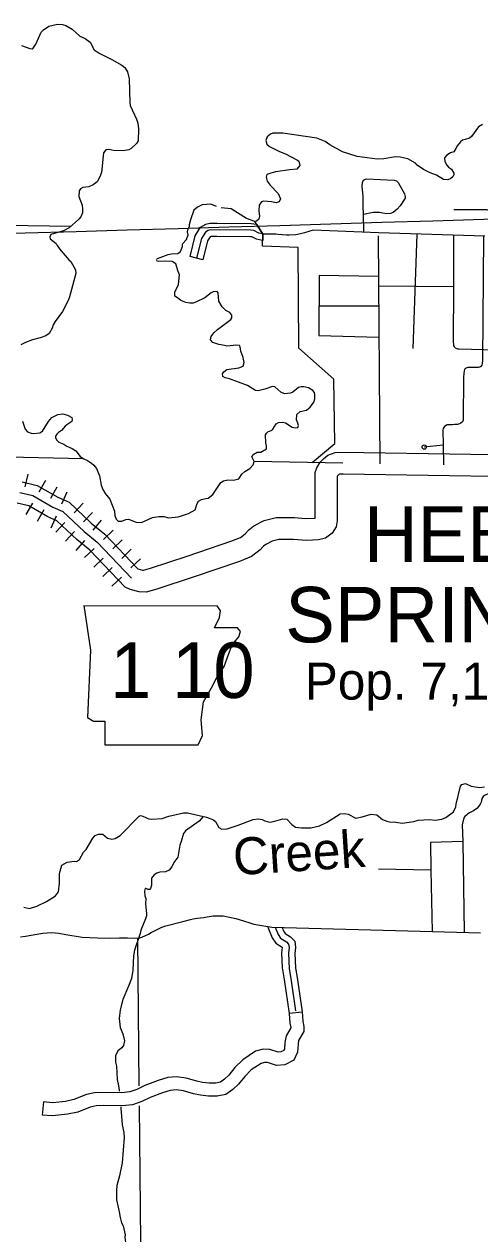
# Model space of a CAD drawing. Extents: x 1212896 to 1368412, y 378476 to 478763.
# Drawn here: x 1293079 to 1298275, y 413498 to 427303 of the extents above; entities that cross this region are included whole.
import ezdxf

# ---------------------------------------------------------------- set-up
doc = ezdxf.new("R2010")
doc.units = 0
for name, color, linetype in [('Level 10', 7, 'Continuous'), ('Level 21', 7, 'Continuous'), ('Level 29', 7, 'Continuous'), ('Level 31', 7, 'Continuous'), ('Level 33', 7, 'Continuous'), ('Level 34', 7, 'Continuous'), ('Level 35', 7, 'Continuous'), ('Level 45', 7, 'Continuous'), ('Level 46', 7, 'Continuous'), ('Level 5', 7, 'Continuous'), ('Level 6', 7, 'Continuous'), ('Level 60', 7, 'Continuous'), ('Level 9', 7, 'Continuous')]:
    doc.layers.add(name, color=color, linetype=linetype)

msp = doc.modelspace()

# ---------------------------------------------------------------- linework, layer by layer
at = {"layer": 'Level 10'}
for points in [[(1293057, 422081), (1293225, 422040), (1293462, 421904), (1293591, 421847), (1293844, 421608), (1293997, 421483), (1294375, 421088), (1294427, 421074), (1294441, 421073), (1294521, 421094), (1294938, 421233), (1295448, 421406), (1295545, 421445), (1295599, 421488), (1295639, 421532), (1295699, 421578), (1295817, 421640), (1295951, 421673), (1296160, 421673), (1296289, 421663), (1296289, 421663), (1296397, 421666), (1296398, 421740), (1296398, 421747), (1296398, 422187), (1296416, 422241), (1296456, 422304), (1296494, 422344), (1296543, 422384), (1296624, 422414), (1296711, 422419), (1299635, 422372)], [(1299627, 422122), (1296717, 422169), (1296676, 422167), (1296668, 422163), (1296664, 422160), (1296654, 422150), (1296648, 422140), (1296648, 421714), (1296650, 421637), (1296637, 421566), (1296593, 421494), (1296514, 421438), (1296434, 421417), (1296297, 421412), (1296150, 421423), (1295982, 421423), (1295907, 421404), (1295834, 421366), (1295809, 421347), (1295770, 421304), (1295672, 421227), (1295535, 421171), (1295017, 420996), (1294591, 420854), (1294468, 420822), (1294390, 420825), (1294287, 420852), (1294229, 420878), (1293826, 421299), (1293679, 421421), (1293451, 421636), (1293349, 421681), (1293131, 421806), (1292998, 421838)]]:
    msp.add_lwpolyline(points, dxfattribs=at)
at = {"layer": 'Level 21'}
for p, q in [((1293760, 420668), (1293836, 420160)), ((1295316, 420608), (1295281, 420667)), ((1295249, 420414), (1295308, 420532)), ((1295308, 420532), (1295316, 420608)), ((1295511, 420414), (1295249, 420414)), ((1295545, 420372), (1295511, 420414)), ((1295528, 420312), (1295545, 420372)), ((1295409, 420109), (1295452, 420219)), ((1295452, 420219), (1295528, 420312)), ((1293836, 420160), (1293802, 419390)), ((1295359, 419974), (1295409, 420109)), ((1295274, 419847), (1295359, 419974)), ((1295215, 419729), (1295274, 419847)), ((1295122, 419568), (1295215, 419729)), ((1295096, 419365), (1295122, 419568)), ((1293802, 419390), (1293870, 419348)), ((1293870, 419348), (1293997, 419348)), ((1293997, 419348), (1293997, 419077)), ((1295113, 419187), (1295096, 419365)), ((1295063, 419077), (1295113, 419187)), ((1293997, 419077), (1295063, 419077))]:
    msp.add_line(p, q, dxfattribs=at)
msp.add_lwpolyline([(1293760, 420668), (1295281, 420667)], dxfattribs=at)
at = {"layer": 'Level 29'}
for p, q in [((1293090, 422022), (1293125, 422167)), ((1293090, 422022), (1293125, 422167)), ((1293251, 421968), (1293325, 422098)), ((1293381, 421893), (1293455, 422023)), ((1293507, 421829), (1293568, 421966)), ((1293507, 421829), (1293568, 421966)), ((1293101, 421708), (1293176, 421838)), ((1293231, 421633), (1293306, 421763)), ((1293647, 421726), (1293750, 421835)), ((1293386, 421555), (1293447, 421692)), ((1293386, 421555), (1293447, 421692)), ((1293441, 421507), (1293544, 421617)), ((1293756, 421623), (1293859, 421732)), ((1293864, 421527), (1293960, 421643)), ((1293864, 421527), (1293960, 421643)), ((1293550, 421405), (1293653, 421514)), ((1293984, 421423), (1294093, 421527)), ((1293673, 421295), (1293769, 421411)), ((1293673, 421295), (1293769, 421411)), ((1294088, 421315), (1294196, 421418)), ((1293768, 421216), (1293876, 421319)), ((1293871, 421107), (1293980, 421211)), ((1294192, 421206), (1294300, 421310)), ((1294192, 421206), (1294300, 421310)), ((1294296, 421098), (1294404, 421202)), ((1293975, 420999), (1294083, 421103)), ((1293975, 420999), (1294083, 421103)), ((1294079, 420891), (1294187, 420994))]:
    msp.add_line(p, q, dxfattribs=at)
msp.add_lwpolyline([(1293028, 421959), (1293178, 421923), (1293406, 421792), (1293521, 421741), (1293761, 421514), (1293911, 421391), (1294303, 420982)], dxfattribs=at)
at = {"layer": 'Level 31'}
for p, q in [((1294972, 424652), (1294971, 424651)), ((1294972, 424652), (1294971, 424651)), ((1295116, 424612), (1294972, 424652))]:
    msp.add_line(p, q, dxfattribs=at)
for points in [[(1294971, 424651), (1295030, 424888), (1295091, 424988), (1295150, 425021), (1295196, 425032), (1295278, 425032)], [(1295797, 424909), (1295753, 424919), (1295696, 424947), (1295663, 424952), (1295205, 424956), (1295178, 424949), (1295146, 424931), (1295102, 424859), (1295045, 424633)], [(1295278, 425032), (1295669, 425028), (1295729, 425020)], [(1295731, 425018), (1295799, 424906), (1295800, 424834)], [(1295277, 424882), (1295214, 424882), (1295206, 424880), (1295199, 424876), (1295170, 424830), (1295117, 424615)], [(1295798, 424834), (1295729, 424849), (1295674, 424876), (1295658, 424878), (1295277, 424882)]]:
    msp.add_lwpolyline(points, dxfattribs=at)
at = {"layer": 'Level 33'}
for points in [[(1296951, 424928), (1296949, 425133), (1296946, 425226), (1296944, 425336), (1296934, 425456), (1296937, 425495), (1296949, 425524), (1296971, 425536), (1296988, 425538), (1297300, 425523), (1297325, 425515), (1297345, 425498), (1297418, 425366), (1297425, 425338), (1297423, 425317), (1297365, 425230), (1297331, 425191), (1297286, 425155), (1297255, 425142), (1297212, 425139), (1297168, 425148), (1297130, 425153), (1297060, 425153), (1296949, 425133)], [(1298331, 424884), (1297119, 424921), (1296374, 424951), (1296275, 424923), (1296229, 424910), (1296175, 424901), (1296102, 424895), (1296072, 424894), (1296025, 424899), (1295977, 424904), (1295948, 424906), (1295916, 424906), (1295877, 424908), (1295844, 424908), (1295803, 424908), (1295797, 424909)], [(1297116, 424886), (1297136, 422287)], [(1297556, 424908), (1297511, 423603)], [(1302241, 423402), (1301921, 423412), (1301013, 423458), (1300953, 423451), (1299977, 423499), (1299789, 423512), (1299689, 423519), (1299621, 423523), (1299556, 423530), (1299467, 423537), (1299138, 423552), (1298614, 423570), (1298321, 423587), (1298038, 423596), (1298038, 423596), (1298029, 423596), (1298016, 423599), (1297998, 423606), (1297996, 423608), (1297987, 423616), (1297980, 423636), (1297974, 423691), (1297980, 424302), (1297980, 424895)], [(1298317, 424885), (1298307, 423465), (1298303, 423430), (1298298, 423410), (1298286, 423396), (1298274, 423389), (1298260, 423387), (1298158, 423384), (1298145, 423384), (1298137, 423384), (1298128, 423382), (1298119, 423378), (1298108, 423371), (1298100, 423361), (1298095, 423346), (1298088, 423277), (1298086, 422783)], [(1297120, 424422), (1296444, 424434), (1296441, 423751), (1297125, 423732)], [(1297121, 424319), (1297980, 424310)], [(1296442, 424088), (1297122, 424089)], [(1297856, 422500), (1297642, 422477)], [(1297856, 422500), (1297863, 422275)], [(1291351, 422398), (1293754, 422345)], [(1296714, 422294), (1295700, 422311)]]:
    msp.add_lwpolyline(points, dxfattribs=at)
msp.add_circle((1297642, 422477), 25, dxfattribs=at)
at = {"layer": 'Level 34'}
for points in [[(1297979, 425189), (1298352, 425189), (1298382, 425176), (1298449, 425118)], [(1298086, 422783), (1298079, 422766), (1298059, 422749), (1298042, 422741), (1298021, 422736), (1297985, 422733), (1297962, 422732), (1297940, 422732), (1297924, 422730), (1297904, 422729), (1297891, 422725), (1297871, 422710), (1297858, 422690), (1297853, 422675), (1297856, 422500)], [(1299052, 418490), (1298452, 418517), (1298419, 418519), (1298398, 418524), (1298375, 418520), (1298351, 418512), (1298329, 418501), (1298315, 418488), (1298304, 418471), (1298295, 418447), (1298289, 418423), (1298278, 418401), (1298266, 418377), (1298241, 418351), (1298203, 418327), (1298158, 418301), (1298136, 418288), (1298125, 418278), (1298105, 418262), (1298093, 418244), (1298074, 418164), (1298081, 417976), (1298097, 416938)], [(1298081, 417976), (1297713, 417966), (1297717, 417647), (1297731, 416948)], [(1297717, 417647), (1297119, 417658)], [(1293038, 416889), (1293095, 416894), (1293224, 416917), (1293293, 416929), (1293391, 416938), (1293475, 416931), (1293554, 416913), (1293740, 416885), (1293914, 416876), (1294056, 416874), (1294166, 416876), (1294192, 416875), (1294257, 416875), (1294332, 416874), (1294397, 416876), (1294421, 416883), (1294495, 416917), (1294526, 416936), (1294579, 416965), (1294649, 416998), (1294696, 417015), (1294888, 417064), (1294977, 417086), (1295007, 417092), (1295053, 417100), (1295127, 417110), (1295164, 417116), (1295233, 417126), (1295271, 417129), (1295348, 417126), (1295419, 417113), (1295491, 417095), (1295580, 417071), (1295654, 417048), (1295696, 417034), (1295767, 417020), (1295905, 416998), (1297735, 416948), (1298282, 416933)]]:
    msp.add_lwpolyline(points, dxfattribs=at)
at = {"layer": 'Level 35'}
for points in [[(1295261, 418202), (1295297, 418134), (1295332, 418118), (1295394, 418120), (1295520, 418162), (1295691, 418227), (1295749, 418234), (1295792, 418227), (1295825, 418212), (1295878, 418198), (1295924, 418205), (1296029, 418234), (1296074, 418229), (1296130, 418169), (1296172, 418139), (1296242, 418132), (1296349, 418133), (1296445, 418156), (1296527, 418193), (1296681, 418292), (1296733, 418297), (1296773, 418288), (1296863, 418243), (1296933, 418257), (1297036, 418288), (1297100, 418280), (1297165, 418226), (1297213, 418208), (1297245, 418200), (1297317, 418195), (1297391, 418183), (1297523, 418205), (1297572, 418219), (1297700, 418227), (1297766, 418220), (1297842, 418229), (1297889, 418251), (1297974, 418316), (1298003, 418371), (1298006, 418400), (1298056, 418606), (1298071, 418628), (1298113, 418637), (1298176, 418606), (1298273, 418590), (1298327, 418600)], [(1293074, 417225), (1293140, 417211), (1293221, 417236), (1293333, 417290), (1293436, 417355), (1293470, 417400), (1293482, 417499), (1293483, 417610), (1293509, 417706), (1293569, 417740), (1293649, 417750), (1293675, 417747), (1293709, 417770), (1293755, 417852), (1293784, 417883), (1293862, 418014), (1293887, 418043), (1293925, 418061), (1293974, 418059), (1294030, 418012), (1294077, 418003), (1294115, 418009), (1294175, 418045), (1294389, 418266), (1294406, 418273), (1294430, 418266), (1294500, 418233), (1294535, 418231), (1294653, 418239), (1294730, 418264), (1294895, 418302), (1294942, 418301), (1295158, 418255), (1295237, 418223), (1295261, 418202)], [(1295120, 418262), (1295075, 418209), (1294919, 418097), (1294894, 418065), (1294870, 417975), (1294854, 417935), (1294830, 417796), (1294784, 417736), (1294764, 417688), (1294732, 417650), (1294690, 417631), (1294627, 417624), (1294592, 417615), (1294562, 417596), (1294531, 417556), (1294530, 417476), (1294521, 417439), (1294511, 417426), (1294493, 417426), (1294465, 417441), (1294460, 417439), (1294450, 417410), (1294453, 417356), (1294465, 417325), (1294463, 417266), (1294474, 417152), (1294473, 417128), (1294463, 417093), (1294408, 416965), (1294400, 416925), (1294335, 416735), (1294325, 416672), (1294318, 416506), (1294301, 416413), (1294270, 416324), (1294203, 416173), (1294172, 416054), (1294160, 415957), (1294175, 415851), (1294204, 415782), (1294222, 415701), (1294212, 415647), (1294193, 415620), (1294145, 415587), (1294119, 415531), (1294119, 415456), (1294130, 415412), (1294138, 415260), (1294156, 415188), (1294160, 415137), (1294163, 415125)], [(1294180, 414946), (1294179, 414931), (1294191, 414790), (1294196, 414741), (1294215, 414654), (1294220, 414596), (1294196, 414310), (1294167, 414160), (1294134, 414048), (1294130, 413991), (1294133, 413887), (1294162, 413751), (1294172, 413683)], [(1294172, 413683), (1294190, 413623), (1294208, 413589), (1294230, 413488), (1294228, 413460), (1294238, 413367), (1294248, 413327), (1294272, 413277), (1294302, 413187), (1294328, 413057), (1294343, 413013), (1294431, 412867), (1294461, 412809), (1294504, 412748)]]:
    msp.add_lwpolyline(points, dxfattribs=at)
at = {"layer": 'Level 45'}
for points in [[(1295859, 416999), (1295906, 416878), (1295948, 416815), (1296022, 416770), (1296022, 416767), (1296015, 416705), (1296022, 416529)], [(1295942, 416997), (1295974, 416914), (1296003, 416871), (1296071, 416830), (1296095, 416804), (1296099, 416767), (1296092, 416702), (1296099, 416523), (1296121, 416413), (1296173, 416044)], [(1296022, 416995), (1296040, 416948), (1296055, 416926), (1296117, 416888), (1296165, 416837), (1296173, 416767), (1296166, 416699), (1296172, 416535)], [(1296022, 416529), (1296023, 416514), (1296045, 416400), (1296101, 416013)], [(1296172, 416535), (1296172, 416531), (1296193, 416425), (1296250, 416030)]]:
    msp.add_lwpolyline(points, dxfattribs=at)
at = {"layer": 'Level 46'}
msp.add_line((1296250, 416026), (1296101, 416013), dxfattribs=at)
for points in [[(1296250, 416030), (1296258, 415924), (1296269, 415866), (1296268, 415809), (1296209, 415706), (1296202, 415663), (1296195, 415571), (1296154, 415481), (1296050, 415427), (1295957, 415419), (1295854, 415452), (1295821, 415454), (1295782, 415443), (1295667, 415368), (1295594, 415295), (1295522, 415208), (1295460, 415147), (1295378, 415089), (1295279, 415068), (1295179, 415069), (1295089, 415079), (1295010, 415096), (1294896, 415129), (1294811, 415140), (1294745, 415134), (1294655, 415106), (1294516, 415054), (1294420, 415007), (1294315, 414972), (1294201, 414959), (1293988, 414961), (1293898, 414957), (1293830, 414944), (1293689, 414888), (1293574, 414862), (1293401, 414843), (1293284, 414854)], [(1296101, 416013), (1296110, 415904), (1296119, 415854), (1296119, 415850), (1296066, 415758), (1296053, 415681), (1296047, 415609), (1296039, 415591), (1296007, 415574), (1295974, 415571), (1295881, 415600), (1295805, 415605), (1295718, 415581), (1295573, 415485), (1295483, 415397), (1295411, 415309), (1295364, 415262), (1295317, 415229), (1295265, 415218), (1295188, 415219), (1295113, 415227), (1295046, 415241), (1294927, 415276), (1294814, 415291), (1294716, 415282), (1294606, 415248), (1294456, 415191), (1294363, 415146), (1294282, 415119), (1294193, 415109), (1293985, 415111), (1293880, 415106), (1293788, 415088), (1293645, 415031), (1293549, 415010), (1293400, 414993), (1293298, 415003), (1293284, 414854)]]:
    msp.add_lwpolyline(points, dxfattribs=at)
at = {"layer": 'Level 5'}
for points in [[(1294372, 416878), (1294388, 415187)], [(1294391, 414957), (1294416, 412243)]]:
    msp.add_lwpolyline(points, dxfattribs=at)
at = {"layer": 'Level 6'}
for points in [[(1288959, 425071), (1293611, 424998)], [(1295799, 424906), (1295709, 425053)], [(1296364, 422300), (1296621, 422517), (1296610, 423252), (1296210, 423607), (1296205, 424755), (1295797, 424768), (1295799, 424906)]]:
    msp.add_lwpolyline(points, dxfattribs=at)
at = {"layer": 'Level 60'}
msp.add_spline([(1257401, 423880), (1274493, 424373), (1311686, 425481), (1319317, 425714)], degree=3, dxfattribs=at)
at = {"layer": 'Level 9'}
for points in [[(1293180, 427030), (1293212, 427076), (1293273, 427213), (1293300, 427240), (1293359, 427280), (1293460, 427303), (1293517, 427298), (1293554, 427288), (1293626, 427248), (1293713, 427166), (1293775, 427139), (1293832, 427097), (1293876, 427011), (1293935, 426971), (1294080, 426901), (1294191, 426836), (1294226, 426809), (1294257, 426758), (1294274, 426679), (1294282, 426408), (1294289, 426376), (1294359, 426221), (1294374, 426175), (1294384, 426110), (1294378, 425973), (1294359, 425943), (1294300, 425885), (1294271, 425871), (1294211, 425858), (1294097, 425862), (1294043, 425872), (1294008, 425869), (1293983, 425834), (1293959, 425612), (1293941, 425563), (1293909, 425504), (1293867, 425468), (1293816, 425446), (1293749, 425438), (1293719, 425423), (1293704, 425401), (1293702, 425336), (1293738, 425239), (1293742, 425191), (1293742, 425151), (1293724, 425104), (1293702, 425079), (1293592, 424979), (1293528, 424944)], [(1293047, 427059), (1293144, 427024), (1293168, 427023), (1293180, 427030)], [(1298305, 426157), (1298261, 426131), (1298181, 426020), (1298159, 426002), (1298107, 425989)], [(1298107, 425989), (1298078, 425980), (1298055, 425960), (1298022, 425920), (1298003, 425883), (1297978, 425846), (1297940, 425834), (1297899, 425809), (1297874, 425777), (1297876, 425735), (1297900, 425696), (1297920, 425673), (1297951, 425649), (1297980, 425604), (1297979, 425584), (1297967, 425561), (1297946, 425544), (1297909, 425528), (1297863, 425531), (1297783, 425581), (1297710, 425607), (1297633, 425645), (1297561, 425694), (1297541, 425718), (1297456, 425765), (1297367, 425786), (1297313, 425791), (1297179, 425767), (1297105, 425764), (1296878, 425793), (1296711, 425847), (1296563, 425928), (1296511, 425963), (1296416, 426004), (1296030, 426059), (1295915, 426061), (1295888, 426049), (1295850, 426019), (1295833, 425975), (1295847, 425935), (1295878, 425907), (1295990, 425851), (1296058, 425825), (1296196, 425750), (1296212, 425739), (1296224, 425692), (1296188, 425650), (1296107, 425642), (1295946, 425617), (1295879, 425600), (1295847, 425586), (1295839, 425559), (1295851, 425510), (1295886, 425466), (1295977, 425370), (1296002, 425311), (1295987, 425274), (1295952, 425265), (1295901, 425276), (1295808, 425285), (1295786, 425276), (1295759, 425238), (1295755, 425174), (1295764, 425107), (1295755, 425078), (1295729, 425057), (1295709, 425053), (1295616, 425086), (1295439, 425196), (1295324, 425209)], [(1295273, 425222), (1295207, 425251), (1295107, 425243), (1295056, 425214), (1295014, 425179), (1294975, 425070), (1294962, 425015), (1294962, 424990)], [(1293528, 424944), (1293383, 424904), (1293371, 424877), (1293375, 424854), (1293443, 424802), (1293454, 424777), (1293480, 424740), (1293586, 424614), (1293610, 424594), (1293663, 424500), (1293669, 424458), (1293596, 424192), (1293583, 424158), (1293517, 424023), (1293430, 423911), (1293410, 423871), (1293399, 423834), (1293363, 423772), (1293324, 423745), (1293260, 423722), (1293173, 423700), (1293092, 423671), (1293040, 423645)], [(1294586, 424616), (1294598, 424631), (1294722, 424675), (1294758, 424684), (1294831, 424685), (1294863, 424708), (1294883, 424766), (1294886, 424796), (1294931, 424846), (1294947, 424900), (1294941, 424935), (1294948, 424967), (1294962, 424990)], [(1296201, 422748), (1296184, 422788), (1296188, 422847), (1296227, 422883), (1296300, 422900), (1296342, 422931), (1296383, 422988), (1296395, 423028), (1296395, 423071), (1296389, 423099), (1296372, 423121), (1296323, 423153), (1296268, 423166), (1296236, 423164), (1296206, 423156), (1296141, 423102), (1296117, 423091), (1296048, 423083), (1296004, 423103), (1295939, 423163), (1295910, 423167), (1295824, 423137), (1295747, 423118), (1295717, 423122), (1295624, 423180), (1295422, 423257), (1295372, 423269), (1295344, 423283), (1295340, 423314), (1295357, 423335), (1295390, 423363), (1295528, 423380), (1295578, 423399), (1295589, 423444), (1295577, 423499), (1295548, 423570), (1295541, 423621), (1295533, 423635), (1295492, 423641), (1295399, 423629), (1295344, 423639), (1295298, 423648), (1295229, 423671), (1295203, 423702), (1295213, 423739), (1295241, 423780), (1295282, 423820), (1295436, 423933), (1295447, 423952), (1295448, 423983), (1295423, 424011), (1295377, 424036), (1295336, 424079), (1295300, 424143), (1295291, 424236), (1295278, 424254), (1295233, 424248), (1295210, 424238), (1295138, 424181), (1295043, 424134), (1295006, 424121), (1294969, 424118), (1294922, 424126), (1294867, 424150), (1294827, 424181), (1294797, 424199), (1294796, 424243), (1294838, 424334), (1294849, 424442), (1294833, 424481), (1294810, 424568), (1294768, 424596), (1294690, 424599), (1294615, 424594), (1294585, 424602)], [(1293059, 422771), (1293091, 422683), (1293118, 422652), (1293158, 422634), (1293186, 422631), (1293257, 422640), (1293288, 422660), (1293356, 422767), (1293395, 422813), (1293461, 422848), (1293521, 422856), (1293574, 422840), (1293621, 422813), (1293627, 422792), (1293623, 422769), (1293564, 422730)], [(1293564, 422730), (1293545, 422716), (1293505, 422667), (1293470, 422644), (1293451, 422624), (1293437, 422603), (1293436, 422581), (1293450, 422557), (1293473, 422534), (1293532, 422510), (1293566, 422486), (1293624, 422462), (1293667, 422435), (1293718, 422371), (1293759, 422342), (1293799, 422324), (1293845, 422295), (1293874, 422271), (1293904, 422233), (1293936, 422147), (1293956, 422044), (1293974, 421994), (1294003, 421947), (1294054, 421881), (1294107, 421744), (1294114, 421696), (1294128, 421654), (1294150, 421632), (1294192, 421633), (1294237, 421652), (1294270, 421655), (1294355, 421619), (1294418, 421617), (1294542, 421675), (1294613, 421685), (1294670, 421683), (1294728, 421669), (1294833, 421682), (1294874, 421692), (1294951, 421718), (1295029, 421760), (1295052, 421832), (1295068, 421859), (1295100, 421878), (1295151, 421891), (1295178, 421893), (1295229, 421934), (1295322, 422071), (1295353, 422093), (1295403, 422103), (1295466, 422099), (1295525, 422114), (1295562, 422168), (1295595, 422199), (1295653, 422234), (1295692, 422274), (1295700, 422311), (1295676, 422367), (1295690, 422394), (1295737, 422418), (1295779, 422418), (1295841, 422457), (1295842, 422492), (1295833, 422526), (1295832, 422618), (1295841, 422636), (1295856, 422650), (1295897, 422668), (1295913, 422682), (1295954, 422741), (1295978, 422759), (1296023, 422763), (1296059, 422755), (1296136, 422703), (1296173, 422695), (1296201, 422700), (1296208, 422724), (1296201, 422748)]]:
    msp.add_lwpolyline(points, dxfattribs=at)

# ---------------------------------------------------------------- texts
at = {"layer": 'Level 21'}
msp.add_text('1 10', height=633.6, dxfattribs=at).set_placement((1294058, 419614))
at = {"layer": 'Level 35'}
msp.add_text('Creek', height=422.4, rotation=3.7498, dxfattribs=at).set_placement((1295475, 417589))
at = {"layer": 'Level 6'}
for s, height, p in [('HEBER', 633.6, (1296954, 421167)), ('SPRINGS', 633.6, (1296057, 420248)), ('Pop. 7,165', 422.4, (1296279, 419595))]:
    msp.add_text(s, height=height, dxfattribs=at).set_placement(p)

doc.saveas('drawing.dxf')
